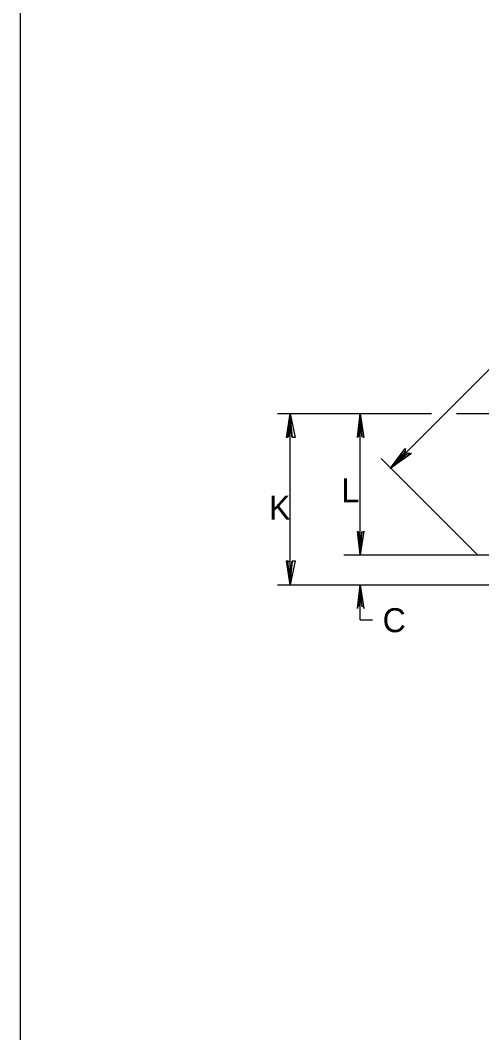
# Model space of a CAD drawing. Extents: x -0.018 to 0.195, y -0.006 to 0.263.
# Drawn here: x 0 to 0.0462, y 0.1026 to 0.2038 of the extents above; entities that cross this region are included whole.
import ezdxf

# ---------------------------------------------------------------- set-up
doc = ezdxf.new("R2010")
doc.units = 0
doc.layers.add('1', color=7, linetype='Continuous')

msp = doc.modelspace()

# ---------------------------------------------------------------- linework, layer by layer
at = {"layer": '1'}
for p, q in [((0, 0.2565), (0, 0)), ((0.037, 0.159), (0.05738, 0.17938)), ((0.02575, 0.1645), (0.04113, 0.1645)), ((0.027, 0.14738), (0.027, 0.1645)), ((0.034, 0.15038), (0.034, 0.1645)), ((0.04363, 0.1645), (0.06237, 0.1645)), ((0.03612, 0.16), (0.04575, 0.15038)), ((0.03238, 0.15038), (0.14313, 0.15038)), ((0.02575, 0.14738), (0.06325, 0.14738)), ((0.034, 0.14388), (0.034, 0.14738)), ((0.034, 0.14388), (0.03525, 0.14388))]:
    msp.add_line(p, q, dxfattribs=at)
for points in [[(0.02675, 0.16212), (0.02687, 0.16225), (0.027, 0.1645), (0.02675, 0.16212), (0.02662, 0.16212), (0.027, 0.1645), (0.02712, 0.16225), (0.02725, 0.16212), (0.027, 0.1645), (0.0275, 0.16212), (0.02725, 0.16212)], [(0.03375, 0.16212), (0.03388, 0.16225), (0.034, 0.1645), (0.03375, 0.16212), (0.03375, 0.16212), (0.034, 0.1645), (0.03413, 0.16225), (0.03438, 0.16212), (0.034, 0.1645), (0.03438, 0.16212), (0.03438, 0.16212)], [(0.039, 0.1605), (0.03875, 0.1605), (0.037, 0.159), (0.039, 0.1605), (0.03913, 0.1605), (0.037, 0.159), (0.03862, 0.16062), (0.0385, 0.16075), (0.037, 0.159), (0.0385, 0.161), (0.0385, 0.16075)], [(0.03438, 0.15263), (0.03413, 0.15263), (0.034, 0.15038), (0.03438, 0.15263), (0.03438, 0.15275), (0.034, 0.15038), (0.03388, 0.15263), (0.03375, 0.15263), (0.034, 0.15038), (0.03375, 0.15275), (0.03375, 0.15263)], [(0.02725, 0.14975), (0.02712, 0.14963), (0.027, 0.14738), (0.02725, 0.14975), (0.0275, 0.14975), (0.027, 0.14738), (0.027, 0.14963), (0.02675, 0.14975), (0.027, 0.14738), (0.02662, 0.14975), (0.02675, 0.14975)], [(0.03375, 0.14513), (0.03388, 0.14525), (0.034, 0.14738), (0.03375, 0.14513), (0.03375, 0.145), (0.034, 0.14738), (0.03413, 0.14525), (0.03438, 0.14513), (0.034, 0.14738), (0.03438, 0.145), (0.03438, 0.14513)]]:
    msp.add_lwpolyline(points, dxfattribs=at)

# ---------------------------------------------------------------- texts
for s, p in [('L', (0.03213, 0.15563)), ('K', (0.02488, 0.15388)), ('C', (0.03625, 0.14263))]:
    msp.add_text(s, height=0.0024, dxfattribs=at).set_placement(p)

doc.saveas('drawing.dxf')
